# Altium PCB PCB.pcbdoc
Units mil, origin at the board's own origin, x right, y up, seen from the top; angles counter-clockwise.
Board outline 2370 x 1665 mil, 2 copper layers (Top Layer, Bottom Layer); 20 components, 27 nets, 104 pads, 57 vias.
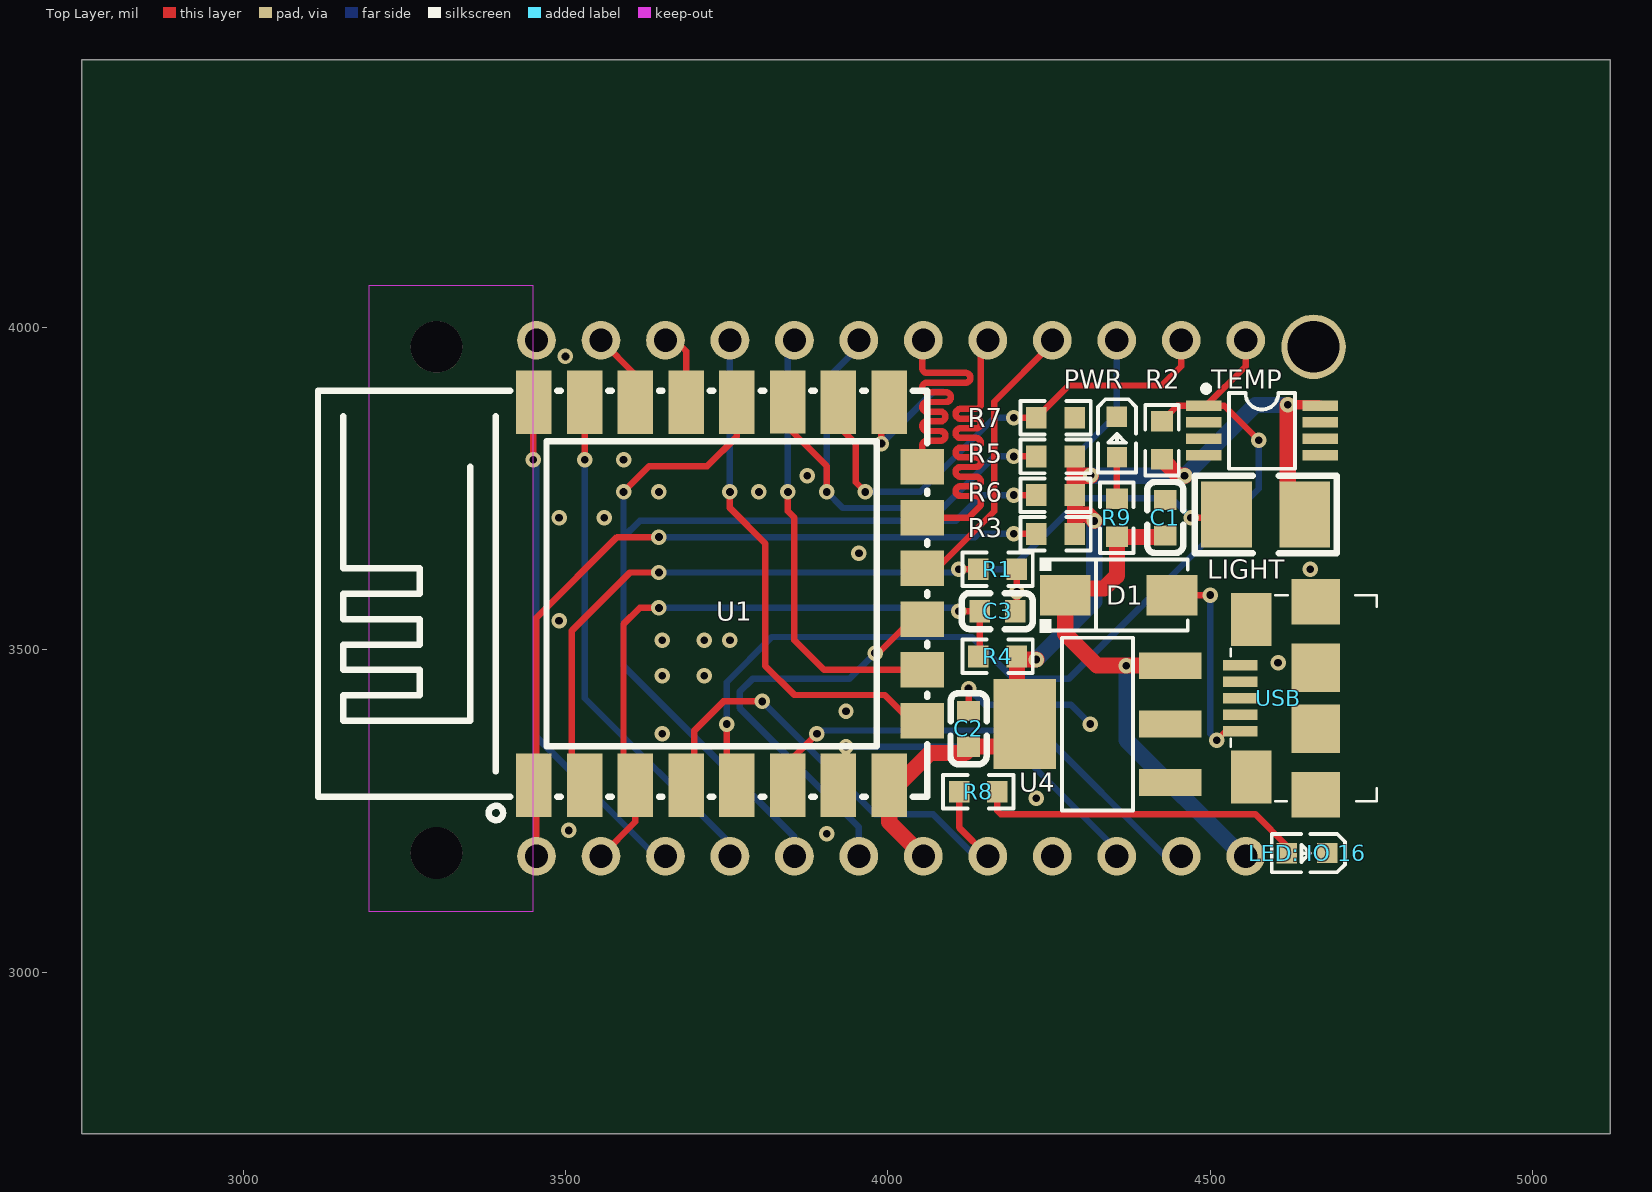
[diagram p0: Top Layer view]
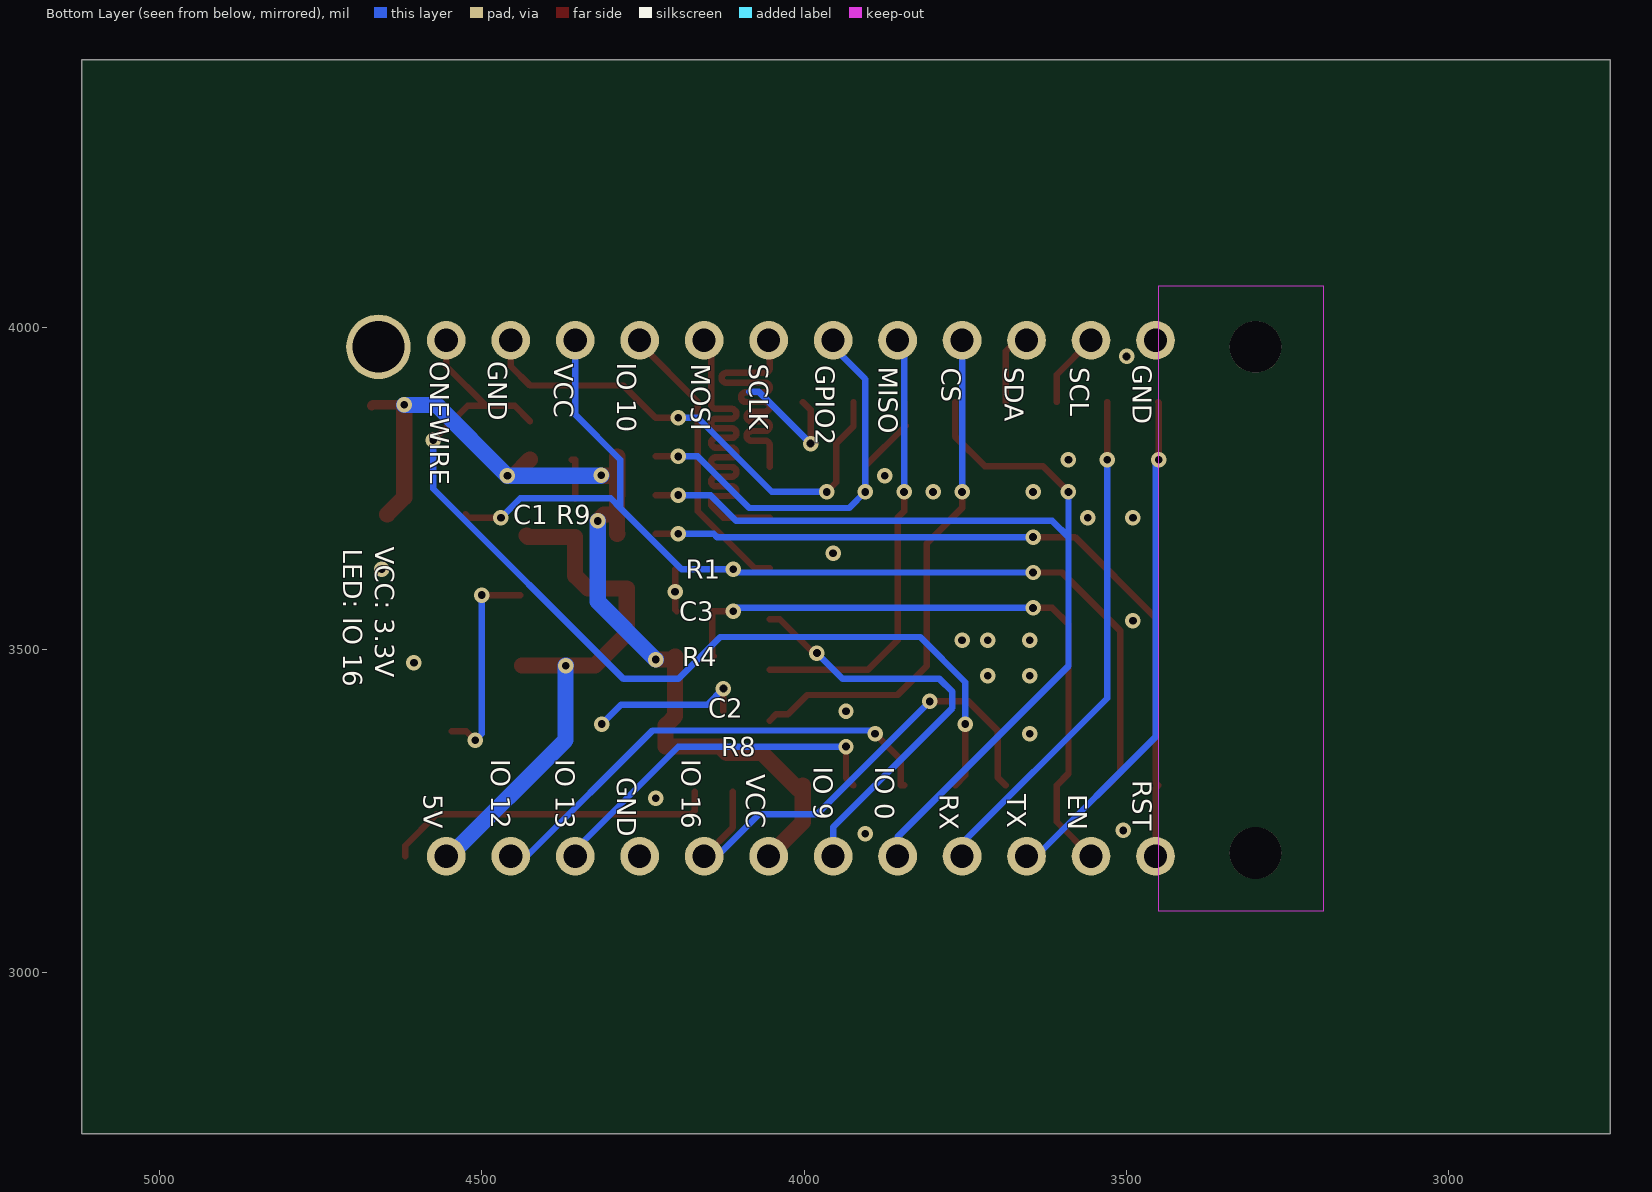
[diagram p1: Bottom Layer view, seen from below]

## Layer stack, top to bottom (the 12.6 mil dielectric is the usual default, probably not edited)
Top Solder: solder mask 0.4, Solder Resist, Dk 3.5
Top Layer: signal copper 1.4
Dielectric 1: dielectric 12.6, FR-4, Dk 4.8
Bottom Layer: signal copper 1.4
Bottom Solder: solder mask 0.4, Solder Resist, Dk 3.5

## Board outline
5120,2750 2750,2750 2750,4415 5120,4415

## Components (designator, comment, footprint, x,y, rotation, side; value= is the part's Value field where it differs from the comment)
C1 "CL10A106MO8NQNC" C0603 4430,3705 r270 top
C2 "CL10A106MO8NQNC" C0603 4125,3377.56 r270 top
C3 "CC0603CRNPO9BN4R7" C0603 4170,3560 r0 top
D1 "1N4007" SMA_L4.3-W2.5-LS5.0-RD 4357.68,3585 r0 top
"LED: IO 16" "XL-1608SURC-06" LED0603-RD_RED 4650,3185 r180 top
LIGHT "GT36549" RES-SMD_L3.6-W2.4 4585.72,3710 r0 top
PWR "XL-1608SURC-06" LED0603-RD_RED 4355,3830 r270 top
R1 "RC0603FR-07100KL" R0603 4170,3625 r0 top
R2 "4.7kΩ" R0603 4425,3825 r270 top
R3 "RC0603FR-0712KL" R0603 4260,3680 r180 top
R4 "RC0603FR-0712KL" R0603 4170,3490 r180 top
R5 "RC0603FR-0712KL" R0603 4260,3800 r180 top
R6 "RC0603FR-0712KL" R0603 4260,3740 r180 top
R7 "RC0603FR-0712KL" R0603 4260,3860 r180 top
R8 "RC0603FR-07100RL" R0603 4140,3280 r0 top
R9 "RC0603FR-07330RL" R0603 4355,3705 r270 top
TEMP "DS18B20U" MSOP-8_L3.0-W3.0-P0.65-LS4.9-BL 4580,3840 r270 top
U1 "ESP-12F(ESP8266MOD)" WIFIM-SMD_ESP-12F-ESP8266MOD 3752.09,3587.09 r0 top
U4 "AMS1117-3.3V" SOT-223_L6.5-W3.5-P2.30-LS7.0-BR 4325,3385 r0 top
USB "10118192-0001LF" MICRO-USB-SMD_10118192-0001LF_1 4605,3425 r90 top

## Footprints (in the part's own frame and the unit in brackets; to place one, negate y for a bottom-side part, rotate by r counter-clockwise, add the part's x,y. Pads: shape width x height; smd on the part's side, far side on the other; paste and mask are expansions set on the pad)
C0603 [mm]
  rect 0.8x0.9 smd: 1(-0.7,0) 2(0.7,0)
  silkscreen extent -1.41,-0.71 1.39,0.72
LED0603-RD_RED [mm]
  rect 0.8x0.8 smd: 1(-0.8,-0.003) 2(0.8,0.003)
  silkscreen extent -1.49,-0.75 1.39,0.76
MICRO-USB-SMD_10118192-0001LF_1 [mm]
  rect 0.4x1.35 smd: 1(-1.3,1.487) 2(-0.65,1.487) 3(0,1.487) 4(0.65,1.487) 5(1.3,1.487)
  rect 1.8x1.9 smd: 6(-3.8,-1.487) 6(3.8,-1.487)
  rect 2.1x1.6 smd: 6(-3.1,1.063) 6(3.1,1.063)
  rect 1.9x1.9 smd: 6(-1.199,-1.487) 6(1.199,-1.487)
  silkscreen extent -4.05,-3.89 4.05,1.86
MSOP-8_L3.0-W3.0-P0.65-LS4.9-BL [mil]
  rect 15.98x55 smd: 1(-38.39,-90.55) 2(-12.8,-90.55) 3(12.8,-90.55) 4(38.39,-90.55) 5(38.39,90.55) 6(12.8,90.55) 7(-12.8,90.55) 8(-38.39,90.55)
  silkscreen extent -70,-91 59,51
R0603 [mil]
  rect 31.75x34.02 smd: 1(-29.66,0) 2(29.66,0)
  silkscreen extent -55,-26 55,26
RES-SMD_L3.6-W2.4 [mm]
  rect 2x2.592 smd: 1(-1.542,0) 2(1.542,0)
  silkscreen extent -2.79,-1.52 2.79,1.52
SMA_L4.3-W2.5-LS5.0-RD [mm]
  rect 2x1.593 smd: 1(-2.1,0) 2(2.1,0)
  silkscreen extent -3.11,-1.48 2.73,1.48
SOT-223_L6.5-W3.5-P2.30-LS7.0-BR [mm]
  rect 2.465x1.05 smd: 1(2.857,-2.3) 2(2.857,0) 3(2.857,2.3)
  rect 2.465x3.54 smd: 4(-2.857,0)
  silkscreen extent -1.4,-3.4 1.4,3.4
WIFIM-SMD_ESP-12F-ESP8266MOD [mm]
  rect 1.4x2.5 smd: 1(-7.651,-7.551) 2(-5.651,-7.551) 3(-3.651,-7.551) 4(-1.651,-7.551) 5(0.349,-7.551) 6(2.349,-7.551) 7(4.349,-7.551) 8(6.349,-7.551) 9(6.349,7.549) 10(4.349,7.55) 11(2.349,7.551) 12(0.349,7.551) 13(-1.651,7.55) 14(-3.651,7.551) 15(-5.651,7.55) 16(-7.651,7.551)
  rect 1.7x1.4 smd: 17(7.651,-5) 18(7.649,-3.002) 19(7.65,-1.003) 20(7.65,0.997) 21(7.65,2.997) 22(7.65,4.997)
  silkscreen extent -16.15,-8.92 7.85,8

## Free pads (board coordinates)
  round 80 hole 80 unplated: 1(3300,3185) 1(3300,3970)
  round 60 hole 36: 1(3455,3180) 1(3455,3980) 1(3555,3180) 1(3555,3980) 1(3655,3180) 1(3655,3980) 1(3755,3180) 1(3755,3980) 1(3855,3180) 1(3855,3980) 1(3955,3180) 1(3955,3980) 1(4055,3180) 1(4055,3980) 1(4155,3180) 1(4155,3980) 1(4255,3180) 1(4255,3980) 1(4355,3180) 1(4355,3980) 1(4455,3180) 1(4455,3980) 1(4555,3180) 1(4555,3980)
  round 100 hole 80: 1(4660,3970)

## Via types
v1: diameter 24.02, hole 12.01, Top Layer to Bottom Layer, 57 vias

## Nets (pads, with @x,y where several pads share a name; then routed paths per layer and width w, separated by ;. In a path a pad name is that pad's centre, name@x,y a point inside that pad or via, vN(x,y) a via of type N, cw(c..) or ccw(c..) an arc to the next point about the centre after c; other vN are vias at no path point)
$1N1610: USB.1 | length 330.9
  Top Layer w10: 4440.36,3585 v1(4500,3585) ; v1(4510,3360) 4523.8,3373.8 USB.1
  Bottom Layer w10: v1(4500,3585) 4500,3370 v1(4510,3360)
$1N6315: "LED: IO 16.2" | length 517.4
  Top Layer w10: 4169.66,3280 4169.66,3250.34 4175,3245 4570,3245 4618.52,3196.48 4618.52,3179.86
$1N6870: PWR.2 R9.1 | length 65.3
  Top Layer w10: R9.1 4355,3795 PWR.2@4360,3795
+5V: D1.1 pad.1@4555,3180 U4.3 | length 853.1
  Top Layer w25: 4430,3677.44 4427.9,3675.34 4355,3675.34 4355,3615 4335,3595 4275,3595 4275,3525 4324.45,3475.55 v1(4369.45,3475.55) U4.3
  Bottom Layer w25: v1(4369.45,3475.55) 4370,3475.55 4370,3360 4550,3180 pad.1@4555,3180
ESP_A0: pad.1@4355,3980 R1.1 U1.2 | length 1682.1
  Top Layer w10: U1.2 3510,3309.42 3510,3530 3600,3620 v1(3645,3620) ; v1(4110,3625) R1.1 ; v1(4470,3705) 4520,3705 4525,3710
  Bottom Layer w10: v1(3645,3620) 4105,3620 v1(4110,3625) 4190,3625 4285,3720 ; pad.1@4355,3980 4355,3865 4285,3795 4285,3720 ; v1(4470,3705) 4440,3735 4300,3735 4285,3720
ESP_CS: pad.1@3755,3980 U1.17 | length 806.2
  Top Layer w10: v1(3755,3745) 3755,3720 3810,3665 3810,3475 3855,3430 3995,3430 4025,3400 4043.54,3400 U1.17
  Bottom Layer w10: v1(3755,3745) pad.1@3755,3980
ESP_EN: C3.1 pad.1@3555,3180 U1.3 | length 1026.7
  Top Layer w10: pad.1@3555,3180 3608.37,3233.37 U1.3 3590,3308.16 3590,3540 3615,3565 v1(3645,3565) ; v1(4110,3560) C3.1 4142.44,3490 4140.34,3490
  Bottom Layer w10: v1(3645,3565) 4105,3565 v1(4110,3560)
ESP_GPIO0: pad.1@3855,3180 U1.12 | length 1607
  Top Layer w10: v1(3590,3745) 3630,3785 3720,3785 3765.85,3830.85 U1.12 ; v1(4195,3740) 4230.34,3740
  Bottom Layer w10: v1(3590,3745) 3590,3675 ; pad.1@3855,3180 3855,3210 3590,3475 3590,3675 ; v1(4195,3740) 4145,3740 4105,3700 3615,3700 3590,3675
ESP_GPIO2: pad.1@3955,3980 U1.11 | length 790.7
  Top Layer w10: U1.11 3844.59,3849.59 3842.5,3847.5 3905,3785 v1(3905,3745) ; v1(4195,3800) 4230.34,3800
  Bottom Layer w10: pad.1@3955,3980 3955,3970 3905,3920 v1(3905,3745) 3930,3720 4085,3720 4165,3800 v1(4195,3800)
  other v1: 4195,3800
ESP_GPIO9: pad.1@3955,3180 U1.19 | length 661.5
  Top Layer w10: v1(3980,3495) 3985,3495 4037.59,3547.59 U1.19
  Bottom Layer w10: pad.1@3955,3180 3955,3225 3770,3410 3770,3435 3790,3455 3940,3455 v1(3980,3495)
ESP_GPIO10: pad.1@4255,3980 U1.20 | length 450.7
  Top Layer w10: U1.20 4076.36,3626.36 4165,3715 4165,3885 4255,3975 pad.1@4255,3980
ESP_GPIO12: pad.1@4455,3180 U1.6 | length 750
  Top Layer w10: U1.6 3850,3289.79 3850,3330 v1(3890,3370)
  Bottom Layer w10: v1(3890,3370) 3895,3375 4235,3375 4430,3180 pad.1@4455,3180
ESP_GPIO13: pad.1@4355,3180 U1.7 | length 561.3
  Top Layer w10: U1.7 3935,3301.46 v1(3935,3350)
  Bottom Layer w10: v1(3935,3350) 4195,3350 4355,3190 pad.1@4355,3180
ESP_GPIO15: pad.1@4455,3980 U1.10 | length 767.4
  Top Layer w10: U1.10 3923.33,3846.67 3950,3820 3950,3760 v1(3965,3745) ; v1(4195,3860) 4230.34,3860 4280.34,3910 4425,3910 4455,3940 pad.1@4455,3980
  Bottom Layer w10: v1(3965,3745) 4050,3745 4165,3860 v1(4195,3860)
ESP_GPIO16: pad.1@4155,3180 R8.1 U1.4 | length 782.1
  Top Layer w10: U1.4 3700,3302.68 3700,3375 3745,3420 v1(3805,3420) ; R8.1 4110.34,3224.66 pad.1@4155,3180
  Bottom Layer w10: v1(3805,3420) 3980,3245 4070,3245 4135,3180 pad.1@4155,3180
ESP_MISO: pad.1@3855,3980 U1.18 | length 690.6
  Top Layer w10: v1(3845,3745) 3845,3715 3855,3705 3855,3515 3901.1,3468.9 U1.18
  Bottom Layer w10: v1(3845,3745) 3845,3970 pad.1@3855,3980
ESP_MOSI: pad.1@4155,3980 U1.21 | length 689.2
  Top Layer w10: U1.21 4125.07,3705.07 4144,3724 4144,3731.12 ccw(c4136.5,3731.12) 4136.5,3738.62 4112.47,3738.62 cw(c4112.47,3746.12) 4104.97,3746.12 cw(c4112.47,3746.12) 4112.47,3753.62 4136.5,3753.62 ccw(c4136.5,3761.12) 4144,3761.12 ccw(c4136.5,3761.12) 4136.5,3768.62 4112.47,3768.62 cw(c4112.47,3776.12) 4104.97,3776.12 cw(c4112.47,3776.12) 4112.47,3783.62 4136.5,3783.62 ccw(c4136.5,3791.12) 4144,3791.12 ccw(c4136.5,3791.12) 4136.5,3798.62 4112.47,3798.62 cw(c4112.47,3806.12) 4104.97,3806.12 cw(c4112.47,3806.12) 4112.47,3813.62 4136.5,3813.62 ccw(c4136.5,3821.12) 4144,3821.12 ccw(c4136.5,3821.12) 4136.5,3828.62 4112.47,3828.62 cw(c4112.47,3836.12) 4104.97,3836.12 cw(c4112.47,3836.12) 4112.47,3843.62 4136.5,3843.62 ccw(c4136.5,3851.12) 4144,3851.12 ccw(c4136.5,3851.12) 4136.5,3858.62 4112.47,3858.62 cw(c4112.47,3866.12) 4104.97,3866.12 cw(c4112.47,3866.12) 4112.47,3873.62 4136.5,3873.62 ccw(c4136.5,3881.12) 4144,3881.12 4144,3959 4160,3975 pad.1@4155,3980
ESP_ONEWIRE: pad.1@4555,3980 R2.1 U1.5 | length 1554
  Top Layer w10: v1(3750,3385) 3750,3305.64 U1.5 ; R2.1 4448.73,3878.39 4489.45,3878.39 4493.39,3878.39 ; pad.1@4555,3980 4555,3940 4493.39,3878.39 ; v1(4575,3825) 4521.61,3878.39 4493.39,3878.39
  Bottom Layer w10: v1(3750,3385) 3750,3450 3820,3520 4130.02,3520 4195.02,3455 4280,3455 4575,3750 v1(4575,3825)
ESP_RST: pad.1@3455,3180 U1.1 | length 1202.6
  Top Layer w10: pad.1@3455,3180 3455,3285.68 U1.1 3455,3293.9 3455,3550 3580,3675 v1(3645,3675) ; v1(4195,3680) 4230.34,3680
  Bottom Layer w10: v1(3645,3675) 4135,3675 4140,3680 v1(4195,3680)
ESP_RX0: pad.1@3755,3180 U1.15 | length 797.7
  Top Layer w10: U1.15 3530,3883.99 v1(3530,3795)
  Bottom Layer w10: v1(3530,3795) 3530,3425 3755,3200 pad.1@3755,3180
ESP_SCL: pad.1@3555,3980 U1.14 | length 117.7
  Top Layer w10: pad.1@3555,3980 3608.37,3926.63 U1.14
ESP_SCLK: pad.1@4055,3980 U1.22 | length 527.4
  Top Layer w10: U1.22 4053.29,3816.93 cw(c4060.79,3816.93) 4060.79,3824.43 4081.7,3824.43 ccw(c4081.7,3831.93) 4089.2,3831.93 ccw(c4081.7,3831.93) 4081.7,3839.43 4060.79,3839.43 cw(c4060.79,3846.93) 4053.29,3846.93 cw(c4060.79,3846.93) 4060.79,3854.43 4081.7,3854.43 ccw(c4081.7,3861.93) 4089.2,3861.93 ccw(c4081.7,3861.93) 4081.7,3869.43 4060.79,3869.43 cw(c4060.79,3876.93) 4053.29,3876.93 cw(c4060.79,3876.93) 4060.79,3884.43 4090.23,3884.43 ccw(c4090.23,3891.93) 4097.73,3891.93 ccw(c4090.23,3891.93) 4090.23,3899.43 4060.79,3899.43 cw(c4060.79,3906.93) 4053.29,3906.93 cw(c4060.79,3906.93) 4060.79,3914.43 4120.5,3914.43 ccw(c4120.5,3921.93) 4128,3921.93 ccw(c4120.5,3921.93) 4120.5,3929.43 4060.79,3929.43 cw(c4060.79,3936.93) 4053.29,3936.93 4053.29,3978.29 pad.1@4055,3980
ESP_SDA: pad.1@3655,3980 U1.13 | length 117.8
  Top Layer w10: pad.1@3655,3980 3670,3980 3687.11,3962.89 U1.13
ESP_TX0: pad.1@3655,3180 | length 798.4
  Top Layer w10: v1(3450,3795) 3450,3883.48 3450.89,3884.37
  Bottom Layer w10: v1(3450,3795) 3455,3790 3455,3365 3640,3180 pad.1@3655,3180
GND: C1.1 C2.1 pad.1@3455,3980 pad.1@4255,3180 pad.1@4660,3970 R7.1 TEMP.4 U1.9 USB.5 USB.6 | length 510.2
  Top Layer w10: v1(3990,3820) 3990,3872.22 U1.9 ; C2.1 v1(4125,3440) ; 4197.56,3560 4200,3562.44 v1(4200,3590) 4200,3624.66 4199.66,3625
  Bottom Layer w10: v1(3990,3820) 4070,3900 4085,3900 ; v1(4125,3440) 4150,3415 4283.93,3415 v1(4313.93,3385)
  other v1: 3905,3215 3505,3220 4230,3270 3650,3370 3935,3405 3650,3460 3715,3460 4605,3480 3650,3515 3715,3515 3755,3515 3490,3545 4655,3625 3955,3650 3490,3705 3560,3705 3645,3745 3800,3745 3875,3770 3590,3795 3500,3955
VCC: LIGHT.2 pad.1@4055,3180 R3.1 R4.1 R5.1 R6.1 TEMP.8 U1.8 U4.4 | length 1611.5
  Top Layer w15: v1(4620,3880) 4668.94,3880 TEMP.8
  Top Layer w25: U1.8 U1.8@4002.07,3284.54 ; pad.1@4055,3180 4002.07,3232.93 U1.8@4002.07,3284.54 ; R4.1 R4.1@4200,3490 ; v1(4230,3485) 4205,3485 R4.1@4200,3490 ; R3.1 4290,3680.34 4290,3710 ; R5.1 4289.66,3770.12 ; v1(4314.53,3770.68) 4314.53,3770.12 4289.66,3770.12 ; v1(4320,3700) 4310,3710 4290,3710 ; 4425,3795.34 4450.34,3770 v1(4460,3770) ; v1(4620,3880) 4620,3736.44 LIGHT.2 ; U1.8@4002.07,3284.54 4009.54,3284.54 4065,3340 4120,3340 4130,3350 4215,3350 4215,3382.5 U4.4 4200,3397.5 R4.1@4200,3490 ; 4289.66,3770.12 R6.1 4290,3739.66 4290,3710
  Bottom Layer w25: v1(4230,3485) 4320,3575 v1(4320,3700) ; v1(4314.53,3770.68) 4315.21,3770 v1(4460,3770) 4570,3880 v1(4620,3880)
"": 
pads on no net: "LED: IO 16.1" C1.2 C2.2 C3.2 D1.2 LIGHT.1 PWR.1 R1.2 R2.2 R3.2 R4.2 R5.2 R6.2 R7.2 R8.2 R9.2 TEMP.1 TEMP.2 TEMP.3 TEMP.5 TEMP.6 TEMP.7 U1.16 U4.1 U4.2 USB.2 USB.3 USB.4

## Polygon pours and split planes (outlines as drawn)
GND on Bottom Layer (solid, remove dead copper): 3000,3000 4865,3000 4865,4165 3000,4165
GND on Top Layer (solid, remove dead copper, pour order 1): 3005,3000 4870,3000 4870,4165 3005,4165

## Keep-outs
Multi-Layer:
  region: 3195,3095 3450,3095 3450,4065 3195,4065

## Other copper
Top Layer:
  pour cut-out net ESP_EN: 3584.94,3178.12 3594.6,3212.53 3587.53,3219.6 3553.12,3209.94
  pour cut-out net VCC: 4056.88,3209.94 4027.78,3224.9 4010.1,3207.22 4025.06,3178.12
  pour cut-out net ESP_GPIO16: 4156.88,3209.94 4122.47,3219.6 4115.4,3212.53 4125.06,3178.12
  pour cut-out net ESP_SDA: 3663.83,3951.33 3683.58,3959.35 3690.65,3966.42 3682.34,3992.34
  pour cut-out net ESP_SCL: 3553.12,3950.06 3587.53,3940.4 3594.6,3947.47 3584.94,3981.88
  pour cut-out net ESP_SCLK: 4031.4,3961.47 4048.29,3936.93 4058.29,3936.93 4076.33,3958.91
  pour cut-out net ESP_MOSI: 4126.79,3969.79 4139,3931.49 4149,3927.55 4168.66,3953.29
  pour cut-out net ESP_GPIO10: 4225.05,3978.34 4217.53,3944.6 4225.44,3938.37 4260.39,3950.49
  pour cut-out net ESP_GPIO15: 4432.5,3960.16 4450,3940 4460,3940 4477.5,3960.16
  pour cut-out net ESP_ONEWIRE: 4532.5,3960.16 4550,3940 4560,3940 4577.5,3960.16
  pour cut-out net ESP_RX0: 3525,3820.15 3535,3820.15 3547.5,3835.15 3512.5,3835.15
  pour cut-out net ESP_SCL: 3597.88,3944.19 3583.74,3944.19 3580.81,3929.44 3635.93,3933.58
  pour cut-out net ESP_SDA: 3692.11,3948.55 3682.11,3948.55 3669.61,3933.55 3704.61,3933.55
  pour cut-out net ESP_GPIO0: 3760.85,3830.85 3770.85,3830.85 3783.35,3835.16 3748.35,3835.16
  pour cut-out net ESP_GPIO2: 3858.35,3824.58 3872.49,3824.58 3872.15,3842.6 3817.03,3835.19
  pour cut-out net ESP_GPIO15: 3938.4,3824.53 3952.54,3824.53 3950.89,3843.86 3895.77,3835.14
  pour cut-out net ESP_SCLK: 4058.29,3816.93 4048.29,3816.93 4035.79,3811.37 4070.79,3811.37
  pour cut-out net ESP_MOSI: 4101.72,3700.07 4101.72,3710.07 4086.72,3722.57 4086.72,3687.57
  pour cut-out net ESP_GPIO9: 4009.19,3526.26 4009.19,3512.12 4034.78,3520.04 4019.79,3554.54
  pour cut-out net ESP_MISO: 4004.77,3463.9 4019.77,3451.4 4019.77,3486.4 4004.77,3473.9
  pour cut-out net ESP_CS: 4009.23,3408.7 4019.83,3362.69 4031.94,3417.8 4009.23,3422.84
  pour cut-out net VCC: 4014.57,3232.93 4029.63,3240.61 3974.51,3240.61 3989.57,3232.93
  pour cut-out net VCC: 4056.15,3313.47 4056.15,3348.82 4002.16,3339.03 4029.63,3240.61
  pour cut-out net ESP_GPIO13: 3940,3350 3930,3350 3917.5,3339 3950.89,3339
  pour cut-out net ESP_GPIO12: 3876.68,3349.61 3862.54,3349.61 3817.03,3339 3872.15,3327.4
  pour cut-out net ESP_ONEWIRE: 3755,3354 3745,3354 3738.29,3339 3767.5,3339
  pour cut-out net ESP_GPIO16: 3695,3354 3682.5,3339 3714.67,3339 3705,3354
  pour cut-out net ESP_EN: 3603.37,3233.37 3613.37,3233.37 3625.87,3240.58 3590.87,3240.58
  pour cut-out net ESP_EN: 3595,3354 3585,3354 3580.81,3339 3607.5,3339
  pour cut-out net ESP_A0: 3515,3354 3505,3354 3502.07,3339 3527.5,3339
  pour cut-out net ESP_A0: 4470.63,3710 4470.63,3700 4485.63,3687.5 4485.63,3722.5
  pour cut-out net ESP_ONEWIRE: 4448.73,3883.39 4448.73,3873.39 4461.95,3870.4 4461.95,3886.38
  pour cut-out net ESP_ONEWIRE: 4521.61,3883.39 4516.95,3886.38 4516.95,3870.4 4521.61,3873.39
  pour cut-out net ESP_ONEWIRE: 4504.92,3896.99 4461.95,3886.38 4516.95,3877.2 4519.06,3896.99
  pour cut-out net VCC: 4441.5,3761.16 4459.18,3778.84 4442.01,3779.46 4407.99,3779.46
  pour cut-out net ESP_ONEWIRE: 4444.41,3881.14 4416.13,3870.54 4442.01,3846.92 4452.27,3874.85
  pour cut-out net +5V: 4369.45,3488.05 4369.45,3463.05 4388.98,3454.88 4388.98,3496.22
  pour cut-out net VCC: 4130,3337.5 4163.98,3315.32 4163.98,3393.75 4130,3362.5
  pour cut-out net VCC: 4187.5,3490 4163.98,3454.68 4243.75,3454.68 4212.5,3490
  pour cut-out net VCC: 4180.22,3337.5 4180.22,3362.5 4142.72,3365.75 4142.72,3334.25
  pour cut-out net $1N1610: 4494.73,3580 4494.73,3590 4479.73,3602.5 4479.73,3567.5
  pour cut-out net +5V: 4262.5,3525 4287.5,3525 4314.37,3553.64 4235.63,3553.64
  pour cut-out net +5V: 4335,3582.5 4335,3607.5 4314.37,3616.36 4314.37,3553.64
  pour cut-out net $1N1610: 4513.54,3356.46 4519.87,3365.93 4519.87,3381.67 4509.26,3366.33
  pour cut-out net +5V: 4374.78,3662.84 4412.28,3661.69 4412.28,3693.19 4374.78,3687.84
  pour cut-out net ESP_RST: 4199.46,3685 4199.46,3675 4214.46,3662.99 4214.46,3697.01
  pour cut-out net VCC: 4277.5,3710 4273.78,3697.01 4305.54,3697.01 4302.5,3710
  pour cut-out net ESP_EN: 4147.44,3522.01 4137.44,3522.01 4124.94,3507.01 4156.22,3507.01
  pour cut-out net VCC: 4187.5,3435.49 4212.5,3435.49 4215.54,3472.99 4183.78,3472.99
  pour cut-out net ESP_GPIO2: 4199.46,3805 4199.46,3795 4214.46,3782.99 4214.46,3817.01
  pour cut-out net VCC: 4302.16,3770.12 4305.54,3782.99 4273.78,3782.99 4277.16,3770.12
  pour cut-out net ESP_GPIO0: 4199.46,3745 4199.46,3735 4214.46,3722.99 4214.46,3757.01
  pour cut-out net VCC: 4302.16,3770.12 4277.16,3770.12 4273.78,3757.01 4305.54,3757.01
  pour cut-out net VCC: 4302.5,3710 4305.54,3722.99 4273.78,3722.99 4277.5,3710
  pour cut-out net ESP_GPIO15: 4199.46,3865 4199.46,3855 4214.46,3842.99 4214.46,3877.01
  pour cut-out net ESP_GPIO15: 4256.82,3879.41 4250.88,3887.61 4222.6,3877.01 4246.22,3851.13
  pour cut-out net ESP_EN: 4147.44,3527.28 4158.19,3542.28 4126.69,3542.28 4137.44,3527.28
  pour cut-out net ESP_EN: 4111.69,3565 4111.69,3555 4126.69,3542.5 4126.69,3577.5
  pour cut-out net $1N6315: 4596.71,3211.22 4602.77,3187.48 4634.27,3200.61 4610.85,3211.22
  pour cut-out net $1N6315: 4164.66,3250.34 4174.66,3250.34 4185.54,3262.99 4153.78,3262.99
  pour cut-out net ESP_GPIO16: 4105.34,3247.99 4115.34,3247.99 4126.22,3262.99 4094.46,3262.99
  pour cut-out net $1N6870: 4350,3767.78 4360,3767.78 4370.89,3782.78 4339.39,3782.78
  pour cut-out net +5V: 4367.5,3621.96 4372.01,3659.46 4337.99,3659.46 4342.5,3621.96
  pour cut-out net +5V: 4409.51,3662.84 4409.51,3687.84 4372.01,3691.22 4372.01,3659.46
  pour cut-out net $1N6870: 4350,3765.54 4337.99,3750.54 4372.01,3750.54 4360,3765.54
  pour cut-out net ESP_A0: 4110,3620 4124.46,3607.99 4124.46,3642.01 4110,3630
  pour cut-out net ESP_RX0: 3539.01,3802.94 3535,3815.41 3525,3815.41 3520.99,3802.94
  pour cut-out net ESP_GPIO0: 3601.98,3744.25 3607.97,3755.9 3600.9,3762.97 3589.25,3756.98
  pour cut-out net ESP_GPIO2: 4202.94,3790.99 4215.41,3795 4215.41,3805 4202.94,3809.01
  pour cut-out net ESP_GPIO15: 4202.94,3850.99 4215.41,3855 4215.41,3865 4202.94,3869.01
  pour cut-out net ESP_GPIO15: 3965.75,3756.98 3954.1,3762.97 3947.03,3755.9 3953.02,3744.25
  pour cut-out net ESP_RST: 4202.94,3670.99 4215.41,3675 4215.41,3685 4202.94,3689.01
  pour cut-out net ESP_EN: 4117.94,3550.99 4130.41,3555 4130.41,3565 4117.94,3569.01
  pour cut-out net ESP_A0: 4117.94,3615.99 4130.41,3620 4130.41,3630 4117.94,3634.01
  pour cut-out net ESP_RST: 3637.06,3684.01 3624.59,3680 3624.59,3670 3637.06,3665.99
  pour cut-out net ESP_A0: 3637.06,3629.01 3624.59,3625 3624.59,3615 3637.06,3610.99
  pour cut-out net ESP_EN: 3637.06,3574.01 3624.59,3570 3624.59,3560 3637.06,3555.99
  pour cut-out net ESP_ONEWIRE: 3740.99,3377.06 3745,3364.59 3755,3364.59 3759.01,3377.06
  pour cut-out net VCC: 4627.94,3870.99 4640.41,3872.5 4640.41,3887.5 4627.94,3889.01
  pour cut-out net ESP_GPIO0: 4202.94,3730.99 4215.41,3735 4215.41,3745 4202.94,3749.01
  pour cut-out net ESP_GPIO16: 3797.06,3429.01 3784.59,3425 3784.59,3415 3797.06,3410.99
  pour cut-out net ESP_A0: 4477.94,3695.99 4490.41,3700 4490.41,3710 4477.94,3714.01
  pour cut-out net $1N1610: 4521.98,3359.25 4527.34,3370.26 4520.26,3377.34 4509.25,3371.98
  pour cut-out net $1N1610: 4492.06,3594.01 4479.59,3590 4479.59,3580 4492.06,3575.99
  pour cut-out net ESP_ONEWIRE: 4575.75,3836.98 4564.1,3842.97 4557.03,3835.9 4563.02,3824.25
  pour cut-out net ESP_GPIO13: 3925.99,3342.06 3930,3329.59 3940,3329.59 3944.01,3342.06
  pour cut-out net ESP_GPIO12: 3878.02,3370.75 3872.03,3359.1 3879.1,3352.03 3890.75,3358.02
  pour cut-out net ESP_GPIO2: 3914.01,3752.94 3910,3765.41 3900,3765.41 3895.99,3752.94
  pour cut-out net ESP_CS: 3745.99,3737.06 3750,3724.59 3760,3724.59 3764.01,3737.06
  pour cut-out net ESP_MISO: 3835.99,3737.06 3840,3724.59 3850,3724.59 3854.01,3737.06
  pour cut-out net ESP_GPIO2: 4202.94,3790.99 4215.41,3795 4215.41,3805 4202.94,3809.01
  pour cut-out net ESP_GPIO9: 3991.23,3490.75 3999.28,3502.21 3994.39,3511.46 3982.81,3506.67
Bottom Layer:
  pour cut-out net ESP_TX0: 3646.17,3208.67 3613.98,3213.09 3609.58,3203.35 3627.66,3167.66
  pour cut-out net ESP_RX0: 3770.77,3205.52 3734.88,3227.19 3724.03,3223.9 3727.71,3192.46
  pour cut-out net ESP_GPIO0: 3877.5,3199.84 3841.07,3231 3826.93,3231 3832.5,3199.84
  pour cut-out net ESP_GPIO9: 3977.5,3199.84 3960,3225 3950,3225 3932.5,3199.84
  pour cut-out net ESP_GPIO16: 4142.54,3207.29 4111.1,3210.97 4107.81,3200.12 4129.48,3164.23
  pour cut-out net ESP_GPIO12: 4438.87,3205.3 4407.94,3209.13 4406.02,3196.9 4431.92,3160.84
  pour cut-out net +5V: 4553.34,3209.95 4524.27,3223.41 4508.69,3203.63 4525.49,3174.61
  pour cut-out net ESP_GPIO13: 4363.88,3208.65 4328.5,3223.57 4319.71,3218.22 4325.46,3185.23
  pour cut-out net ESP_MISO: 3827.17,3968.79 3840,3931.21 3850,3927.67 3869.6,3953.79
  pour cut-out net ESP_GPIO2: 3925.46,3974.77 3919.71,3941.78 3928.5,3936.43 3963.88,3951.35
  pour cut-out net ESP_A0: 4332.5,3960.16 4350,3929 4360,3929 4377.5,3960.16
  pour cut-out net ESP_CS: 3732.5,3960.16 3750,3929 3760,3929 3777.5,3960.16
  pour cut-out net ESP_RX0: 3520.99,3787.06 3525,3774.59 3535,3774.59 3539.01,3787.06
  pour cut-out net ESP_GPIO0: 3580.99,3737.06 3585,3724.59 3595,3724.59 3599.01,3737.06
  pour cut-out net ESP_GPIO2: 4187.06,3809.01 4174.59,3805 4174.59,3795 4187.06,3790.99
  pour cut-out net ESP_GPIO15: 4187.06,3869.01 4174.59,3865 4174.59,3855 4187.06,3850.99
  pour cut-out net ESP_GPIO15: 3972.94,3735.99 3985.41,3740 3985.41,3750 3972.94,3754.01
  pour cut-out net ESP_RST: 4187.06,3689.01 4174.59,3685 4174.59,3675 4187.06,3670.99
  pour cut-out net ESP_EN: 4106.53,3571.5 4092.13,3570 4087.55,3560 4099.03,3555.12
  pour cut-out net ESP_A0: 4099.03,3629.88 4087.55,3625 4092.13,3615 4106.53,3613.5
  pour cut-out net ESP_A0: 4117.94,3615.99 4130.41,3620 4130.41,3630 4117.94,3634.01
  pour cut-out net ESP_RST: 3652.94,3665.99 3665.41,3670 3665.41,3680 3652.94,3684.01
  pour cut-out net ESP_A0: 3652.94,3610.99 3665.41,3615 3665.41,3625 3652.94,3629.01
  pour cut-out net ESP_EN: 3652.94,3555.99 3665.41,3560 3665.41,3570 3652.94,3574.01
  pour cut-out net ESP_ONEWIRE: 3759.01,3392.94 3755,3405.41 3745,3405.41 3740.99,3392.94
  pour cut-out net ESP_GPIO0: 4187.06,3749.01 4174.59,3745 4174.59,3735 4187.06,3730.99
  pour cut-out net ESP_GPIO16: 3804.25,3408.02 3815.9,3402.03 3822.97,3409.1 3816.98,3420.75
  pour cut-out net ESP_A0: 4470.75,3716.98 4459.1,3722.97 4452.03,3715.9 4458.02,3704.25
  pour cut-out net $1N1610: 4510.75,3371.98 4503.54,3373.54 4496.46,3366.46 4498.02,3359.25
  pour cut-out net $1N1610: 4490.99,3577.06 4495,3564.59 4505,3564.59 4509.01,3577.06
  pour cut-out net ESP_ONEWIRE: 4565.99,3817.06 4570,3804.59 4580,3804.59 4584.01,3817.06
  pour cut-out net ESP_GPIO13: 3942.94,3340.99 3955.41,3345 3955.41,3355 3942.94,3359.01
  pour cut-out net ESP_GPIO12: 3900.97,3365.12 3912.45,3370 3907.87,3380 3893.47,3381.5
  pour cut-out net ESP_GPIO2: 3914.01,3752.94 3910,3765.41 3900,3765.41 3895.99,3752.94
  pour cut-out net ESP_GPIO2: 3904.25,3733.02 3915.9,3727.03 3922.97,3734.1 3916.98,3745.75
  pour cut-out net ESP_CS: 3764.01,3752.94 3760,3765.41 3750,3765.41 3745.99,3752.94
  pour cut-out net ESP_MISO: 3854.01,3752.94 3850,3765.41 3840,3765.41 3835.99,3752.94
  pour cut-out net ESP_GPIO2: 4187.06,3809.01 4174.59,3805 4174.59,3795 4187.06,3790.99
  pour cut-out net ESP_GPIO9: 3968.02,3495.75 3962.03,3484.1 3969.1,3477.03 3980.75,3483.02

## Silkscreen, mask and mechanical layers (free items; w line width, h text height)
Bottom Overlay:
  text "ONEWIRE" at 4579.99,3947.62 h29.2 r90
  text "GND" at 4489.99,3947.49 h29.2 r90
  text "IO 10" at 4289.99,3945.06 h29.2 r90
  text "SCLK" at 4084.99,3943.78 h29.2 r90
  text "MOSI" at 4174.99,3943.78 h29.2 r90
  text "VCC" at 4387.49,3943.54 h29.2 r90
  text "GND" at 3489.99,3942.49 h29.2 r90
  text "GPIO2" at 3981.86,3941.37 h29.2 r90
  text "SCL" at 3587.49,3938.54 h29.2 r90
  text "MISO" at 3884.36,3939.04 h29.2 r90
  text "SDA" at 3688.74,3938.02 h29.2 r90
  text "CS" at 3786.24,3937.79 h29.2 r90
  text "VCC: 3.3V" at 4664.99,3660.19 h29.2 r90
  text "R1" at 4183.79,3609.99 h29.2
  text "IO 16" at 4189.99,3330.06 h29.2 r90
  text "IO 13" at 4384.99,3330.06 h29.2 r90
  text "IO 12" at 4484.99,3330.06 h29.2 r90
  text "IO 0" at 3889.99,3318.78 h29.2 r90
  text "IO 9" at 3984.99,3318.78 h29.2 r90
  text "VCC" at 4089.99,3307.49 h29.2 r90
  text "GND" at 4289.99,3302.49 h29.2 r90
  text "RST" at 3489.99,3297.49 h29.2 r90
  text "EN" at 3589.99,3276.21 h29.2 r90
  text "TX" at 3684.99,3276.21 h29.2 r90
  text "RX" at 3789.99,3276.21 h29.2 r90
  text "5V" at 4589.99,3276.21 h29.2 r90
Mechanical 1:
  lines w10: 3230,3120 4730,3120 4730,4045 3230,4045 3230,3120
